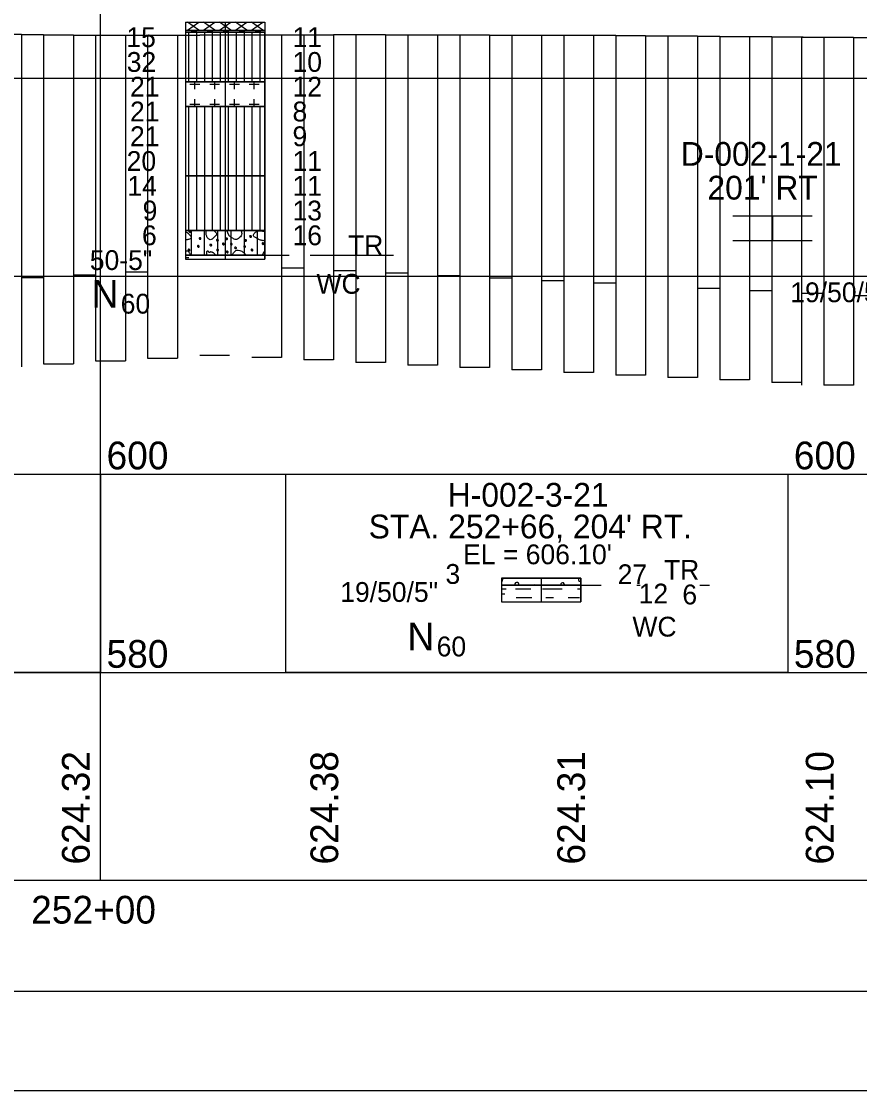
# Model space of a CAD drawing. Extents: x -2280229 to 1306, y -58886 to 440.
# Drawn here: x 377 to 461.6, y 0 to 107.9 of the extents above; entities that cross this region are included whole.
import ezdxf

# ---------------------------------------------------------------- set-up
doc = ezdxf.new("R2010")
doc.units = 0
for name, color, linetype in [('BR_P_Sub_Deep_Object', 7, 'Continuous'), ('Default', 7, 'Continuous'), ('GT_Project_Soil_Layers', 7, 'Continuous'), ('GT_Project_Text', 7, 'Continuous'), ('SC_Scratch1', 7, 'Continuous'), ('SC_Scratch2', 7, 'Continuous'), ('SC_Scratch3', 7, 'Continuous'), ('SC_Scratch4', 7, 'Continuous'), ('SC_Scratch5', 7, 'Continuous'), ('SC_Scratch6', 7, 'Continuous'), ('SC_Scratch9', 7, 'Continuous'), ('SH_Minor_Grid_Line', 7, 'Continuous')]:
    doc.layers.add(name, color=color, linetype=linetype)

msp = doc.modelspace()

# ---------------------------------------------------------------- linework, layer by layer
at = {"layer": 'BR_P_Sub_Deep_Object'}
for p, q in [((373.98, 106.62), (376.98, 106.62)), ((376.98, 106.62), (376.98, 73.06)), ((376.98, 106.59), (379.23, 106.59)), ((379.23, 106.59), (379.23, 73.35)), ((379.23, 106.57), (382.23, 106.57)), ((382.23, 106.57), (382.23, 73.35)), ((382.23, 106.55), (384.48, 106.55)), ((384.48, 106.55), (384.48, 73.65)), ((384.48, 106.53), (387.48, 106.53)), ((387.48, 106.54), (387.48, 73.65)), ((389.73, 106.55), (389.73, 73.94)), ((389.73, 106.55), (392.73, 106.55)), ((392.73, 106.55), (392.73, 73.94)), ((392.73, 106.55), (394.98, 106.55)), ((394.98, 106.56), (397.98, 106.56)), ((397.98, 106.56), (400.23, 106.56)), ((400.23, 106.57), (403.23, 106.57)), ((403.23, 106.58), (403.23, 74)), ((403.23, 106.58), (405.48, 106.58)), ((405.48, 106.58), (405.48, 73.75)), ((408.48, 106.59), (408.48, 73.75)), ((408.48, 106.59), (410.73, 106.59)), ((410.73, 106.59), (410.73, 73.5)), ((410.73, 106.59), (413.73, 106.59)), ((413.73, 106.59), (413.73, 73.5)), ((413.73, 106.58), (415.98, 106.58)), ((415.98, 106.58), (415.98, 73.24)), ((415.98, 106.57), (418.98, 106.57)), ((418.98, 106.57), (418.98, 73.24)), ((418.98, 106.56), (421.23, 106.56)), ((421.23, 106.56), (421.23, 72.99)), ((421.23, 106.56), (424.23, 106.56)), ((424.23, 106.56), (424.23, 72.99)), ((424.23, 106.55), (426.48, 106.55)), ((426.48, 106.55), (426.48, 72.74)), ((426.48, 106.54), (429.48, 106.54)), ((429.48, 106.54), (429.48, 72.74)), ((429.48, 106.53), (431.73, 106.53)), ((431.73, 106.53), (431.73, 72.49)), ((431.73, 106.53), (434.73, 106.53)), ((434.73, 106.53), (434.73, 72.49)), ((434.73, 106.52), (436.98, 106.52)), ((436.98, 106.52), (436.98, 72.23)), ((436.98, 106.5), (439.98, 106.5)), ((439.98, 106.48), (442.23, 106.48)), ((439.98, 106.48), (439.98, 72.23)), ((442.23, 106.46), (445.23, 106.46)), ((442.23, 106.46), (442.23, 71.98)), ((445.23, 106.46), (445.23, 71.98)), ((445.23, 106.43), (447.48, 106.43)), ((447.48, 106.43), (447.48, 71.73)), ((447.48, 106.41), (450.48, 106.41)), ((450.48, 106.41), (450.48, 71.73)), ((450.48, 106.39), (452.73, 106.39)), ((452.73, 106.39), (452.73, 71.47)), ((452.73, 106.37), (455.89, 106.37)), ((455.73, 106.37), (455.73, 71.22)), ((455.73, 106.34), (457.98, 106.34)), ((457.98, 106.34), (457.98, 71.22)), ((457.98, 106.32), (460.98, 106.32)), ((460.98, 106.32), (460.98, 71.22)), ((376.98, 82.06), (379.23, 82.06)), ((382.23, 82.35), (384.48, 82.35)), ((387.48, 82.65), (389.73, 82.65)), ((405.48, 83), (403.23, 83)), ((410.73, 82.75), (408.48, 82.75)), ((415.98, 82.5), (413.73, 82.5)), ((421.23, 82.24), (418.98, 82.24)), ((426.48, 81.99), (424.23, 81.99)), ((431.73, 81.74), (429.48, 81.74)), ((436.98, 81.49), (434.73, 81.49)), ((447.48, 80.98), (445.23, 80.98)), ((452.73, 80.73), (450.48, 80.73)), ((457.98, 80.47), (455.73, 80.47)), ((463.23, 80.22), (460.98, 80.22)), ((384.48, 73.65), (387.48, 73.65)), ((389.73, 73.94), (392.73, 73.94)), ((394.98, 74.24), (397.98, 74.24)), ((403.23, 74), (400.23, 74)), ((408.48, 73.75), (405.48, 73.75)), ((413.73, 73.5), (410.73, 73.5)), ((379.23, 73.35), (382.23, 73.35)), ((418.98, 73.24), (415.98, 73.24)), ((424.23, 72.99), (421.23, 72.99)), ((429.48, 72.74), (426.48, 72.74)), ((434.73, 72.49), (431.73, 72.49)), ((439.98, 72.23), (436.98, 72.23)), ((445.23, 71.98), (442.23, 71.98)), ((450.48, 71.73), (447.48, 71.73)), ((455.73, 71.47), (452.73, 71.47)), ((460.98, 71.22), (457.98, 71.22))]:
    msp.add_line(p, q, dxfattribs=at)
at = {"layer": 'Default'}
for points in [[(335.25, 62.21), (384.98, 62.21), (384.98, 42.21), (335.25, 42.21)], [(403.66, 62.21), (454.35, 62.21), (454.35, 42.21), (403.66, 42.21)]]:
    msp.add_lwpolyline(points, close=True, dxfattribs=at)
at = {"layer": 'GT_Project_Soil_Layers'}
for p, q in [((393.55, 107.03), (393.55, 107.03)), ((393.74, 107.03), (394.9, 107.83)), ((394.9, 107.03), (393.74, 107.83)), ((393.74, 106.83), (394.9, 107.03)), ((394.9, 106.83), (393.74, 107.03)), ((395.36, 107.03), (396.51, 107.83)), ((396.51, 107.03), (395.36, 107.83)), ((395.36, 106.83), (396.51, 107.03)), ((396.51, 106.83), (395.36, 107.03)), ((396.98, 107.03), (398.13, 107.83)), ((398.13, 107.03), (396.98, 107.83)), ((396.98, 106.83), (398.13, 107.03)), ((398.13, 106.83), (396.98, 107.03)), ((398.59, 107.03), (399.75, 107.83)), ((399.75, 107.03), (398.59, 107.83)), ((398.59, 106.83), (399.75, 107.03)), ((399.75, 106.83), (398.59, 107.03)), ((400.21, 107.03), (401.36, 107.83)), ((401.36, 107.03), (400.21, 107.83)), ((400.21, 106.83), (401.36, 107.03)), ((401.36, 106.83), (400.21, 107.03)), ((393.55, 106.83), (393.55, 106.83)), ((393.89, 104.33), (393.89, 106.83)), ((394.69, 104.33), (394.69, 106.83)), ((395.49, 104.33), (395.49, 106.83)), ((396.29, 104.33), (396.29, 106.83)), ((397.09, 104.33), (397.09, 106.83)), ((397.89, 104.33), (397.89, 106.83)), ((398.69, 104.33), (398.69, 106.83)), ((399.49, 104.33), (399.49, 106.83)), ((400.29, 104.33), (400.29, 106.83)), ((401.09, 104.33), (401.09, 106.83)), ((393.89, 101.83), (393.89, 104.33)), ((394.69, 101.83), (394.69, 104.33)), ((395.49, 101.83), (395.49, 104.33)), ((396.29, 101.83), (396.29, 104.33)), ((397.09, 101.83), (397.09, 104.33)), ((397.89, 101.83), (397.89, 104.33)), ((398.69, 101.83), (398.69, 104.33)), ((399.49, 101.83), (399.49, 104.33)), ((400.29, 101.83), (400.29, 104.33)), ((401.09, 101.83), (401.09, 104.33)), ((393.99, 101.58), (394.99, 101.58)), ((394.49, 101.08), (394.49, 101.83)), ((395.99, 101.58), (396.49, 101.58)), ((396.49, 101.83), (396.49, 101.08)), ((396.49, 101.58), (396.99, 101.58)), ((397.99, 101.58), (398.99, 101.58)), ((398.49, 101.08), (398.49, 101.83)), ((399.99, 101.58), (400.99, 101.58)), ((400.49, 101.08), (400.49, 101.83)), ((393.89, 95.83), (393.89, 99.33)), ((393.99, 99.58), (394.99, 99.58)), ((394.49, 99.33), (394.49, 100.08)), ((394.69, 95.83), (394.69, 99.33)), ((395.49, 95.83), (395.49, 99.33)), ((395.99, 99.58), (396.49, 99.58)), ((396.29, 95.83), (396.29, 99.33)), ((396.49, 100.08), (396.49, 99.33)), ((396.49, 99.58), (396.99, 99.58)), ((397.09, 95.83), (397.09, 99.33)), ((397.89, 95.83), (397.89, 99.33)), ((397.99, 99.58), (398.99, 99.58)), ((398.49, 99.33), (398.49, 100.08)), ((398.69, 95.83), (398.69, 99.33)), ((399.49, 95.83), (399.49, 99.33)), ((399.99, 99.58), (400.99, 99.58)), ((400.29, 95.83), (400.29, 99.33)), ((400.49, 99.33), (400.49, 100.08)), ((401.09, 95.83), (401.09, 99.33)), ((393.89, 92.33), (393.89, 95.83)), ((394.69, 92.33), (394.69, 95.83)), ((395.49, 92.33), (395.49, 95.83)), ((396.29, 92.33), (396.29, 95.83)), ((397.09, 92.33), (397.09, 95.83)), ((397.89, 92.33), (397.89, 95.83)), ((398.69, 92.33), (398.69, 95.83)), ((399.49, 92.33), (399.49, 95.83)), ((400.29, 92.33), (400.29, 95.83)), ((401.09, 92.33), (401.09, 95.83)), ((393.89, 89.58), (393.89, 92.33)), ((394.69, 89.58), (394.69, 92.33)), ((395.49, 89.58), (395.49, 92.33)), ((396.29, 89.58), (396.29, 92.33)), ((397.09, 89.58), (397.09, 92.33)), ((397.89, 89.58), (397.89, 92.33)), ((398.69, 89.58), (398.69, 92.33)), ((399.49, 89.58), (399.49, 92.33)), ((400.29, 89.58), (400.29, 92.33)), ((401.09, 89.58), (401.09, 92.33)), ((393.89, 86.83), (393.89, 89.58)), ((394.69, 86.83), (394.69, 89.58)), ((395.49, 86.83), (395.49, 89.58)), ((396.29, 86.83), (396.29, 89.58)), ((397.09, 86.83), (397.09, 89.58)), ((397.89, 86.83), (397.89, 89.58)), ((398.69, 86.83), (398.69, 89.58)), ((399.49, 86.83), (399.49, 89.58)), ((400.29, 86.83), (400.29, 89.58)), ((401.09, 86.83), (401.09, 89.58)), ((394.15, 85.58), (394.15, 86.83)), ((395.48, 85.58), (395.48, 86.83)), ((396.82, 85.58), (396.82, 86.83)), ((398.15, 85.58), (398.15, 86.83)), ((399.49, 85.58), (399.49, 86.83)), ((400.82, 85.58), (400.82, 86.83)), ((394.15, 84.33), (394.15, 85.58)), ((395.48, 84.33), (395.48, 85.58)), ((396.82, 84.33), (396.82, 85.58)), ((398.15, 84.33), (398.15, 85.58)), ((399.49, 84.33), (399.49, 85.58)), ((400.82, 84.33), (400.82, 85.58)), ((393.89, 84.06), (393.55, 84.06)), ((425.93, 50.62), (425.44, 50.62)), ((425.78, 50.12), (425.44, 50.12)), ((428.41, 50.62), (426.84, 50.62)), ((428.49, 49.75), (426.92, 49.75)), ((431.58, 50.62), (429.59, 50.62)), ((430.69, 49.75), (429.91, 49.75)), ((433.33, 49.75), (432.18, 49.75)), ((433.44, 50.62), (433.11, 50.62))]:
    msp.add_line(p, q, dxfattribs=at)
for points in [[(401.55, 106.83), (393.55, 106.83), (393.55, 101.83), (401.55, 101.83)], [(393.55, 99.33), (401.55, 99.33), (401.55, 101.83), (393.55, 101.83)], [(401.55, 99.33), (393.55, 99.33), (393.55, 92.33), (401.55, 92.33)], [(393.55, 86.83), (401.55, 86.83), (401.55, 92.33), (393.55, 92.33)], [(393.55, 84.33), (401.55, 84.33), (401.55, 86.83), (393.55, 86.83)], [(393.55, 83.93), (401.55, 83.93), (401.55, 84.33), (393.55, 84.33)], [(433.44, 51.73), (425.44, 51.73), (425.44, 51.03), (433.44, 51.03)], [(425.44, 49.33), (433.44, 49.33), (433.44, 51.03), (425.44, 51.03)]]:
    msp.add_lwpolyline(points, close=True, dxfattribs=at)
for centre, start, end in [((425.4, 51.58), 282.1335, 0), ((425.4, 51.58), 282.1335, 0), ((425.4, 51.58), 0, 56.2695), ((425.4, 51.58), 0, 56.2695), ((426.99, 51.11), 0, 202.9388), ((426.99, 51.11), 0, 202.9388), ((426.99, 51.11), 337.0612, 0), ((426.99, 51.11), 337.0612, 0), ((428.82, 50.86), 64.4442, 115.5558), ((428.82, 50.86), 64.4442, 115.5558), ((431.61, 51.07), 0, 189.7254), ((431.61, 51.07), 0, 189.7254), ((431.61, 51.07), 350.2746, 0), ((431.61, 51.07), 350.2746, 0), ((433.4, 51.58), 123.7305, 282.1335), ((433.4, 51.58), 123.7305, 282.1335)]:
    msp.add_arc(centre, 0.191, start, end, dxfattribs=at)
for points, degree in [([(393.55, 86.69), (393.58, 86.68), (393.61, 86.66), (393.63, 86.65), (393.79, 86.57), (393.9, 86.45), (394.01, 86.32), (394.08, 86.24), (394.16, 86.07), (394.07, 86.02), (393.94, 85.94), (393.79, 85.91), (393.63, 85.87), (393.61, 85.86), (393.58, 85.86), (393.55, 85.85)], 3), ([(396.42, 86.83), (396.49, 86.75), (396.56, 86.67), (396.63, 86.59), (396.76, 86.45), (396.53, 86.23), (396.37, 86.07), (396.24, 85.94), (396.04, 85.86), (395.92, 85.95), (395.82, 86.01), (395.74, 86.12), (395.69, 86.24), (395.63, 86.39), (395.62, 86.55), (395.64, 86.71), (395.65, 86.75), (395.66, 86.79), (395.67, 86.83)], 3), ([(397.98, 86.26), (397.89, 86.45), (397.8, 86.64), (397.71, 86.83)], 2), ([(399.15, 86.83), (399.16, 86.78), (399.18, 86.74), (399.19, 86.7), (399.24, 86.51), (399.19, 86.28), (399.01, 86.1), (398.82, 85.93), (398.56, 85.87), (398.39, 85.99), (398.25, 86.08), (398.11, 86.17), (397.98, 86.26)], 3), ([(400.04, 86.83), (400.04, 86.83), (400.04, 86.83), (400.04, 86.83), (400.02, 86.81), (400, 86.8), (399.98, 86.8), (399.97, 86.8), (399.95, 86.81), (399.93, 86.82), (399.93, 86.82), (399.92, 86.83), (399.92, 86.83)], 3), ([(400.88, 85.95), (400.75, 86.03), (400.62, 86.1), (400.49, 86.18), (400.37, 86.25), (400.43, 86.48), (400.55, 86.58), (400.69, 86.7), (400.84, 86.77), (400.99, 86.78), (401.18, 86.79), (401.37, 86.77), (401.55, 86.69)], 3), ([(401.55, 85.84), (401.46, 85.81), (401.36, 85.77), (401.27, 85.81), (401.14, 85.85), (401.01, 85.9), (400.88, 85.95)], 3), ([(394.05, 84.33), (394.03, 84.42), (394, 84.5), (393.93, 84.59), (393.85, 84.69), (393.72, 84.76), (393.63, 84.73), (393.6, 84.72), (393.58, 84.71), (393.55, 84.69)], 3), ([(396.58, 84.33), (396.55, 84.39), (396.51, 84.45), (396.45, 84.5), (396.37, 84.57), (396.3, 84.59), (396.22, 84.62), (396.17, 84.63), (396.12, 84.64), (396.08, 84.65), (396.04, 84.66), (395.99, 84.6), (395.95, 84.6), (395.91, 84.61), (395.89, 84.69), (395.85, 84.71), (395.82, 84.72), (395.75, 84.75), (395.72, 84.72), (395.7, 84.7), (395.68, 84.67), (395.66, 84.65)], 3), ([(395.66, 84.65), (395.66, 84.54), (395.66, 84.44), (395.67, 84.33)], 2), ([(398.22, 84.37), (398.33, 84.48), (398.45, 84.6), (398.56, 84.71), (398.72, 84.87), (399.04, 84.82), (399.24, 84.71), (399.38, 84.64), (399.49, 84.54), (399.6, 84.4), (399.62, 84.38), (399.64, 84.35), (399.65, 84.33)], 3), ([(398.23, 84.33), (398.23, 84.34), (398.22, 84.36), (398.22, 84.37)], 2), ([(400.82, 84.33), (400.82, 84.34), (400.83, 84.35), (400.84, 84.36), (400.86, 84.38), (400.88, 84.37), (400.89, 84.37), (400.91, 84.37), (400.92, 84.38), (400.93, 84.37), (400.95, 84.35), (400.96, 84.34), (400.98, 84.33)], 3), ([(401.33, 84.38), (401.33, 84.37), (401.33, 84.35), (401.32, 84.33)], 2), ([(401.55, 84.69), (401.48, 84.64), (401.41, 84.58), (401.38, 84.5), (401.36, 84.46), (401.35, 84.42), (401.33, 84.38)], 3)]:
    msp.add_open_spline(points, degree=degree, dxfattribs=at)
for points in [[(394.05, 86.75), (394.07, 86.71), (394.04, 86.66), (393.99, 86.64), (393.94, 86.66), (393.9, 86.7), (393.88, 86.74), (393.91, 86.79), (393.96, 86.8), (394, 86.79), (394.05, 86.75)], [(394.92, 85.25), (394.94, 85.21), (394.92, 85.16), (394.86, 85.14), (394.81, 85.16), (394.77, 85.19), (394.75, 85.23), (394.78, 85.29), (394.83, 85.29), (394.87, 85.29), (394.92, 85.25)], [(395.08, 86.04), (395.1, 86), (395.08, 85.95), (395.02, 85.93), (394.97, 85.95), (394.93, 85.98), (394.92, 86.02), (394.95, 86.08), (395, 86.08), (395.04, 86.08), (395.08, 86.04)], [(396.18, 85.37), (396.2, 85.34), (396.17, 85.29), (396.12, 85.26), (396.07, 85.28), (396.03, 85.32), (396.01, 85.36), (396.04, 85.41), (396.09, 85.42), (396.13, 85.42), (396.18, 85.37)], [(396.85, 85.86), (396.87, 85.82), (396.84, 85.77), (396.79, 85.75), (396.74, 85.77), (396.7, 85.8), (396.68, 85.84), (396.71, 85.9), (396.76, 85.9), (396.8, 85.9), (396.85, 85.86)], [(397.45, 85.49), (397.46, 85.45), (397.44, 85.4), (397.39, 85.38), (397.33, 85.39), (397.29, 85.43), (397.28, 85.47), (397.31, 85.53), (397.36, 85.53), (397.4, 85.53), (397.45, 85.49)], [(397.78, 86), (397.79, 85.97), (397.77, 85.92), (397.72, 85.9), (397.66, 85.91), (397.62, 85.95), (397.61, 85.99), (397.64, 86.04), (397.69, 86.05), (397.73, 86.05), (397.78, 86)], [(398.24, 85.48), (398.26, 85.44), (398.24, 85.4), (398.18, 85.37), (398.13, 85.39), (398.09, 85.43), (398.08, 85.47), (398.11, 85.52), (398.16, 85.53), (398.2, 85.52), (398.24, 85.48)], [(399.59, 85.22), (399.61, 85.18), (399.58, 85.14), (399.53, 85.11), (399.48, 85.13), (399.44, 85.17), (399.42, 85.21), (399.45, 85.26), (399.5, 85.27), (399.54, 85.26), (399.59, 85.22)], [(399.69, 85.84), (399.7, 85.81), (399.68, 85.76), (399.63, 85.73), (399.57, 85.75), (399.53, 85.79), (399.52, 85.83), (399.55, 85.88), (399.6, 85.89), (399.64, 85.89), (399.69, 85.84)], [(400.19, 86.25), (400.21, 86.21), (400.18, 86.16), (400.13, 86.14), (400.08, 86.16), (400.04, 86.19), (400.02, 86.23), (400.05, 86.29), (400.1, 86.29), (400.14, 86.29), (400.19, 86.25)], [(401.45, 85.53), (401.46, 85.49), (401.44, 85.44), (401.39, 85.42), (401.34, 85.43), (401.3, 85.47), (401.28, 85.51), (401.31, 85.57), (401.36, 85.57), (401.4, 85.57), (401.45, 85.53)], [(393.98, 84.88), (394, 84.84), (393.98, 84.79), (393.92, 84.77), (393.87, 84.78), (393.83, 84.82), (393.81, 84.86), (393.85, 84.92), (393.89, 84.92), (393.93, 84.92), (393.98, 84.88)], [(396.87, 84.88), (396.88, 84.84), (396.86, 84.79), (396.81, 84.77), (396.75, 84.78), (396.71, 84.82), (396.7, 84.86), (396.73, 84.92), (396.78, 84.92), (396.82, 84.92), (396.87, 84.88)], [(397.84, 84.68), (397.86, 84.64), (397.83, 84.59), (397.78, 84.57), (397.73, 84.59), (397.69, 84.63), (397.67, 84.67), (397.7, 84.72), (397.75, 84.73), (397.79, 84.72), (397.84, 84.68)], [(398.67, 85.09), (398.69, 85.05), (398.67, 85.01), (398.61, 84.98), (398.56, 85), (398.52, 85.04), (398.5, 85.08), (398.54, 85.13), (398.58, 85.14), (398.62, 85.13), (398.67, 85.09)], [(400.34, 84.88), (400.36, 84.85), (400.34, 84.8), (400.28, 84.77), (400.23, 84.79), (400.19, 84.83), (400.17, 84.87), (400.2, 84.92), (400.25, 84.93), (400.29, 84.93), (400.34, 84.88)]]:
    msp.add_spline(points, degree=3, dxfattribs=at)
at = {"layer": 'GT_Project_Text'}
msp.add_lwpolyline([(0, 0), (680, 0), (680, 440), (0, 440)], close=True, dxfattribs=at)
at = {"layer": 'SC_Scratch1'}
msp.add_lwpolyline([(30, 430), (670, 430), (670, 10), (30, 10)], close=True, dxfattribs=at)
at = {"layer": 'SC_Scratch2'}
for p, q in [((393.55, 107.83), (401.55, 107.83)), ((393.55, 107.83), (393.55, 83.93)), ((393.55, 107.03), (401.55, 107.03)), ((397.55, 107.83), (397.55, 83.93)), ((401.55, 107.83), (401.55, 83.93)), ((387.48, 106.54), (389.73, 106.54)), ((393.55, 106.83), (401.55, 106.83)), ((405.48, 106.58), (408.48, 106.58)), ((460.98, 106.3), (463.23, 106.3)), ((393.55, 101.83), (401.55, 101.83)), ((393.55, 99.33), (401.55, 99.33)), ((393.55, 92.33), (401.55, 92.33)), ((448.8, 88.31), (456.8, 88.31)), ((452.8, 88.31), (452.8, 85.81)), ((393.55, 86.83), (401.55, 86.83)), ((448.8, 85.81), (456.8, 85.81)), ((393.55, 84.33), (401.55, 84.33)), ((393.55, 83.93), (401.55, 83.93)), ((425.44, 51.73), (433.44, 51.73)), ((425.44, 51.73), (425.44, 49.33)), ((425.44, 51.03), (433.44, 51.03)), ((429.44, 51.73), (429.44, 49.33)), ((433.44, 51.73), (433.44, 49.33)), ((425.44, 49.33), (433.44, 49.33))]:
    msp.add_line(p, q, dxfattribs=at)
at = {"layer": 'SC_Scratch3'}
for p, q in [((401.55, 84.33), (404.02, 84.33)), ((406.12, 84.33), (414.55, 84.33)), ((387.01, 80.43), (387.01, 80.43)), ((433.44, 51.03), (435.5, 51.03)), ((439.1, 51.03), (439.45, 51.03)), ((445.47, 51.03), (446.44, 51.03)), ((418.9, 45.83), (418.9, 45.83))]:
    msp.add_line(p, q, dxfattribs=at)
at = {"layer": 'SC_Scratch5'}
msp.add_line((603.01, 21.22), (45.43, 21.22), dxfattribs=at)
at = {"layer": 'SH_Minor_Grid_Line'}
for p, q in [((384.98, 21.22), (384.98, 162.21)), ((45.43, 102.21), (603.01, 102.21)), ((45.43, 82.21), (603.01, 82.21)), ((45.43, 62.21), (603.01, 62.21)), ((45.43, 42.21), (603.01, 42.21))]:
    msp.add_line(p, q, dxfattribs=at)

# ---------------------------------------------------------------- texts
at = {"layer": 'SC_Scratch2'}
for s, p in [('15', (387.58, 105.33)), ('11', (404.35, 105.33)), ('32', (387.62, 102.83)), ('10', (404.35, 102.83)), ('21', (387.95, 100.33)), ('12', (404.35, 100.33)), ('21', (387.95, 97.83)), ('8', (404.35, 97.83)), ('21', (387.95, 95.33)), ('9', (404.35, 95.33)), ('20', (387.61, 92.83)), ('11', (404.35, 92.83)), ('14', (387.69, 90.33)), ('11', (404.35, 90.33)), ('9', (389.22, 87.83)), ('13', (404.35, 87.83)), ('6', (389.16, 85.33)), ('16', (404.35, 85.33)), ('TR', (409.95, 84.33)), ('50-5"', (383.89, 82.83)), ('WC', (406.77, 80.43)), ('19/50/5"', (454.59, 79.58))]:
    msp.add_text(s, height=2, dxfattribs=at).set_placement(p)
at = {"layer": 'SC_Scratch3'}
for s, height, p in [('D-002-1-21', 2.4, (443.54, 93.35)), ("201' RT", 2.4, (446.23, 89.94)), ('N', 2.8, (384.07, 79.03)), ('60', 2, (387.01, 78.43)), ('H-002-3-21', 2.4, (420.02, 58.94)), ("EL = 606.10'", 2, (421.57, 53.13)), ('N', 2.8, (415.95, 44.43)), ('60', 2, (418.9, 43.83))]:
    msp.add_text(s, height=height, dxfattribs=at).set_placement(p)
at = {"layer": 'SC_Scratch4'}
msp.add_text("STA. 252+66, 204' RT.", height=2.4, dxfattribs=at).set_placement((412.04, 55.74))
at = {"layer": 'SC_Scratch5'}
for s, p in [('3', (419.79, 51.15)), ('19/50/5"', (409.17, 49.33))]:
    msp.add_text(s, height=2, dxfattribs=at).set_placement(p)
at = {"layer": 'SC_Scratch6'}
for s, p in [('27', (437.17, 51.12)), ('TR', (441.84, 51.56)), ('12', (439.29, 49.17)), ('6', (443.7, 49.08))]:
    msp.add_text(s, height=2, dxfattribs=at).set_placement(p)
at = {"layer": 'SC_Scratch9'}
for s, height, p in [('600', 2.8, (385.58, 62.71)), ('600', 2.8, (454.95, 62.71)), ('WC', 2, (438.66, 45.83)), ('580', 2.8, (385.58, 42.68)), ('580', 2.8, (454.95, 42.68)), ('252+00', 2.8, (377.97, 16.86))]:
    msp.add_text(s, height=height, dxfattribs=at).set_placement(p)
for s, p in [('624.32', (383.88, 22.82)), ('624.38', (408.96, 22.82)), ('624.31', (433.88, 22.82)), ('624.10', (458.96, 22.82))]:
    msp.add_text(s, height=2.8, rotation=90, dxfattribs=at).set_placement(p)

doc.saveas('drawing.dxf')
